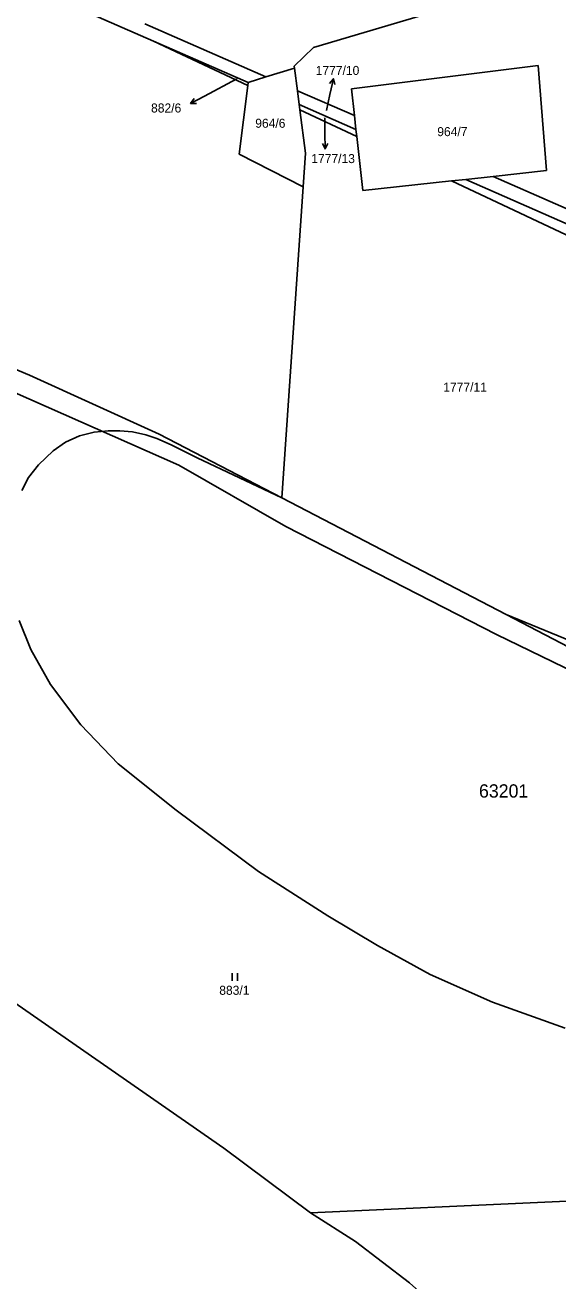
# Model space of a CAD drawing. Extents: x -546762 to -540209, y -1046851 to -1035694.
# Drawn here: x -543546.4 to -543446.1, y -1042242 to -1042005.7 of the extents above; entities that cross this region are included whole.
import ezdxf

# ---------------------------------------------------------------- set-up
doc = ezdxf.new("R2010")
doc.units = 0
for name, color, linetype in [('Vrstva 1', 7, 'Continuous'), ('Vrstva 16', 7, 'Continuous'), ('Vrstva 18', 7, 'Continuous'), ('Vrstva 25', 7, 'Continuous'), ('Vrstva 52', 7, 'Continuous'), ('Vrstva 53', 7, 'Continuous'), ('Vrstva 6', 7, 'Continuous')]:
    doc.layers.add(name, color=color, linetype=linetype)

msp = doc.modelspace()

# ---------------------------------------------------------------- linework, layer by layer
at = {"layer": 'Vrstva 1'}
msp.add_line((-543457.62, -1042120.33), (-543439.71, -1042129.08), dxfattribs=at)
for points in [[(-543465.15, -1042001.89), (-543492.11, -1042009.87)], [(-543492.11, -1042009.87), (-543495.75, -1042013.37)], [(-543501.07, -1042015.4), (-543495.69, -1042013.74)], [(-543495.75, -1042013.37), (-543495.69, -1042013.74)], [(-543495.69, -1042013.74), (-543495.13, -1042018)], [(-543449.78, -1042013.23), (-543484.97, -1042017.66)], [(-543448.19, -1042033.03), (-543449.78, -1042013.23)], [(-543506.12, -1042029.94), (-543504.47, -1042016.99)], [(-543504.47, -1042016.99), (-543504.4, -1042016.43)], [(-543504.4, -1042016.43), (-543501.07, -1042015.4)], [(-543495.13, -1042018), (-543494.79, -1042020.62)], [(-543484.97, -1042017.66), (-543484.4, -1042022.69)], [(-543494.79, -1042020.62), (-543494.66, -1042021.59)], [(-543494.66, -1042021.59), (-543493.59, -1042029.73)], [(-543484.4, -1042022.69), (-543484.11, -1042025.28)], [(-543484.11, -1042025.28), (-543483.96, -1042026.61)], [(-543483.96, -1042026.61), (-543482.82, -1042036.79)], [(-543494.04, -1042036.12), (-543506.12, -1042029.94)], [(-543493.59, -1042029.73), (-543494.04, -1042036.12)], [(-543458.28, -1042034.13), (-543448.19, -1042033.03)], [(-543482.82, -1042036.79), (-543466.12, -1042034.98)], [(-543466.12, -1042034.98), (-543463.43, -1042034.69)], [(-543463.43, -1042034.69), (-543458.28, -1042034.13)], [(-543494.04, -1042036.12), (-543498.1, -1042094.62)], [(-543620.53, -1042040.17), (-543545.64, -1042071.53)], [(-543551.76, -1042073.37), (-543517.46, -1042088.49)], [(-543545.64, -1042071.53), (-543521.15, -1042082.63)], [(-543521.15, -1042082.63), (-543498.1, -1042094.62)], [(-543517.46, -1042088.49), (-543497.32, -1042100.03)], [(-543455.82, -1042116.61), (-543498.1, -1042094.62)], [(-543497.32, -1042100.03), (-543457.62, -1042120.33)], [(-543455.82, -1042116.61), (-543416.16, -1042137.24)], [(-543440.02, -1042123.02), (-543455.82, -1042116.61)]]:
    msp.add_lwpolyline(points, dxfattribs=at)
at = {"layer": 'Vrstva 16'}
for p, q in [((-543489, -1042018.68), (-543488.35, -1042015.75)), ((-543512.61, -1042019), (-543515.26, -1042020.4)), ((-543489.94, -1042025.95), (-543489.91, -1042028.95))]:
    msp.add_line(p, q, dxfattribs=at)
for points in [[(-543506.52, -1042015.79), (-543512.61, -1042019)], [(-543489.06, -1042016.62), (-543488.35, -1042015.75), (-543488.08, -1042016.84)], [(-543514.15, -1042020.38), (-543515.26, -1042020.4), (-543514.61, -1042019.49)], [(-543489.67, -1042021.72), (-543489, -1042018.68)], [(-543489.97, -1042023.1), (-543489.94, -1042025.95)], [(-543489.42, -1042027.94), (-543489.91, -1042028.95), (-543490.42, -1042027.96)]]:
    msp.add_lwpolyline(points, dxfattribs=at)
at = {"layer": 'Vrstva 25'}
for p, q in [((-543507.45, -1042185.57), (-543507.45, -1042184.07)), ((-543506.45, -1042185.57), (-543506.45, -1042184.07))]:
    msp.add_line(p, q, dxfattribs=at)
at = {"layer": 'Vrstva 52'}
for points in [[(-543547.07, -1042093.22), (-543545.81, -1042090.77), (-543543.91, -1042088.44), (-543541.18, -1042085.79), (-543538.85, -1042084.12), (-543536.2, -1042082.98), (-543533.43, -1042082.26), (-543530.82, -1042082.03)], [(-543530.82, -1042082.03), (-543528.61, -1042081.99), (-543526.23, -1042082.22)], [(-543526.23, -1042082.22), (-543523.7, -1042082.78), (-543521.65, -1042083.49), (-543518.92, -1042084.68), (-543514.01, -1042087.07), (-543498.1, -1042094.62), (-543455.82, -1042116.61), (-543416.16, -1042137.24)], [(-543677.4, -1042113.26), (-543674.7, -1042113.54), (-543671.17, -1042114.51), (-543667.93, -1042115.75), (-543635.29, -1042133.98), (-543563.87, -1042178.94), (-543509.01, -1042217.06), (-543492.66, -1042229.18)], [(-543444.68, -1042194.43), (-543458.37, -1042189.58), (-543470.12, -1042184.37), (-543480.05, -1042178.92), (-543489.4, -1042173.31), (-543502.48, -1042164.95), (-543517.98, -1042153.44), (-543528.88, -1042144.72), (-543535.91, -1042137.33), (-543541.63, -1042129.74), (-543545.37, -1042123.17), (-543547.58, -1042117.7)], [(-543492.66, -1042229.18), (-543404.36, -1042225.21), (-543395.23, -1042224.86), (-543386.37, -1042224.31), (-543376.61, -1042222.23), (-543369.41, -1042219.95), (-543362.29, -1042217.39), (-543353.71, -1042213.72), (-543346.3, -1042208.73), (-543340.7, -1042204.78), (-543334.12, -1042199.52), (-543330.82, -1042195.84), (-543329.24, -1042193.11), (-543328.49, -1042191.41), (-543327.93, -1042189.83), (-543327.7, -1042188.15), (-543327.7, -1042186.45), (-543327.85, -1042184.63), (-543328.13, -1042183.01), (-543328.68, -1042181.35), (-543329.36, -1042179.94)], [(-543431.47, -1042353.05), (-543427.75, -1042337.7), (-543427.06, -1042333.41), (-543426.23, -1042328.77), (-543425.82, -1042323.44), (-543425.89, -1042317.97), (-543426.37, -1042313.12), (-543427.41, -1042309.11), (-543429.21, -1042304.6), (-543431.08, -1042300.24), (-543433.08, -1042295.33), (-543435.23, -1042290.27), (-543439.01, -1042283.46), (-543444.7, -1042274.5), (-543452.33, -1042264.56), (-543463.72, -1042251.6), (-543474.01, -1042242.39), (-543484.19, -1042234.63), (-543492.66, -1042229.18)]]:
    msp.add_lwpolyline(points, dxfattribs=at)
at = {"layer": 'Vrstva 6'}
for points in [[(-543589.38, -1041979.37), (-543522.23, -1042008.65)], [(-543501.07, -1042015.4), (-543523.87, -1042005.44)], [(-543504.4, -1042016.43), (-543522.23, -1042008.65)], [(-543522.23, -1042008.65), (-543504.47, -1042016.99)], [(-543484.4, -1042022.69), (-543495.13, -1042018)], [(-543494.79, -1042020.62), (-543484.11, -1042025.28)], [(-543483.96, -1042026.61), (-543494.66, -1042021.59)], [(-543411.14, -1042060.79), (-543466.12, -1042034.98)], [(-543463.43, -1042034.69), (-543405.12, -1042060.31)], [(-543399.51, -1042059.86), (-543458.28, -1042034.13)]]:
    msp.add_lwpolyline(points, dxfattribs=at)

# ---------------------------------------------------------------- texts
at = {"layer": 'Vrstva 16'}
for s, p in [('1777/10', (-543491.69, -1042015.03)), ('882/6', (-543522.71, -1042022.1)), ('1777/13', (-543492.52, -1042031.62))]:
    msp.add_text(s, height=1.7, dxfattribs=at).set_placement(p)
at = {"layer": 'Vrstva 18'}
for s, height, p in [('882/6', 0.1, (-543506.71, -1042015.79)), ('1777/10', 0.1, (-543489.91, -1042021.72)), ('964/6', 1.7, (-543503.08, -1042024.97)), ('1777/13', 0.1, (-543490.2, -1042023.1)), ('964/7', 1.7, (-543468.79, -1042026.55)), ('1777/11', 1.7, (-543467.66, -1042074.64)), ('883/1', 1.7, (-543509.86, -1042188.17))]:
    msp.add_text(s, height=height, dxfattribs=at).set_placement(p)
at = {"layer": 'Vrstva 53'}
msp.add_text('63201', height=2.5, dxfattribs=at).set_placement((-543460.93, -1042151.05))

doc.saveas('drawing.dxf')
